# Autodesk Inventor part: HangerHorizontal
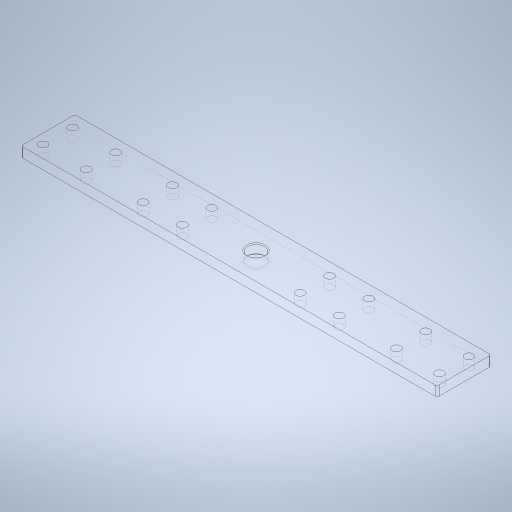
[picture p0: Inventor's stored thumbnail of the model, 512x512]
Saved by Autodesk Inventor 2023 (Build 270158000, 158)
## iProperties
Created: 2023-11
Part Number: HangerHorizontal
Material: Generic
Document SubType Name: Modeling
Designer: tornqvih
Density: 1 g/cm^3
Appearance: Default
Mass: 221.761 g
Surface Area: 586.557 cm^2
Volume: 221.761 cm^3
Author: tornqvih
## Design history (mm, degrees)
sketch "Sketch1"
  geometry: L1 (212, 27.5)-(-212, 27.5); L2 (-212, 27.5)-(-212, -27.5); L3 (-212, -27.5)-(212, -27.5); L4 (212, -27.5)-(212, 27.5); L5 (212, 27.5)-(-212, -27.5); L6 (-212, 27.5)-(212, -27.5); 1 further point
  constraints: 12 end point, 2 midpoint, 2 parallel, 1 horizontal, 1 perpendicular
  dimensions: "d0" = 424 distance of L1.start L1.end; "d1" = 55 distance of L3.end L1.start
extrude "Extrusion1" new body sketch "Sketch1" distance "d2" = 10; taper "d3" = 0 deg
sketch "Sketch2"
  geometry: L1 (-296.8, 0)-(296.8, 0) reference; L2 (0, 38.5)-(0, -38.5) reference; L3 (-212, -27.5)-(212, -27.5) reference; L4 (-212, 27.5)-(-212, -27.5) reference; L5 (212, 27.5)-(-212, 27.5) reference; 17 further points
  constraints: 12 symmetric about line, 3 horizontal alignment
  dimensions: "d23" = 44 distance of point (-158, 15) point (-202, 15); "d27" = 100 distance from line of L2 point (-100, 15); "d28" = 40 distance of point (-60, 15) point (-100, 15); "d29" = 30 distance of point (-202, -15) point (-202, 15); "d30" = 10 distance from line of L4 point (-202, 15)
hole "Hole1" sketch "Sketch2" at (-202, -15), (-202, 15), (202, -15), (202, 15), (-158, 15), (-158, -15), (158, 15), (158, -15), (-100, 15), (-60, 15), (-100, -15), (-60, -15)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 diameter "d6" = 8.5; stored, may be unused: countersink angle "d10" = 90 deg, drill point angle "d12" = 118 deg; dims "d7" = 6, "d8" = 4, "d9" = 2, "d11" = 8
fillet "Fillet1" dims "d13" = 2
sketch "Sketch3"
  geometry: 2 further points
  constraints: 1 coincident
hole "Hole2" sketch "Sketch3" at (0, 0) diameter "d14" = 17; stored, may be unused: countersink angle "d18" = 90 deg, drill point angle "d20" = 118 deg; dims "d15" = 6, "d16" = 4, "d17" = 2, "d19" = 8
chamfer "Chamfer1" distance "d24" = 1; stored, may be unused: second distance "d25" = 2, angle "d26" = 45 deg
body "Solid1"
